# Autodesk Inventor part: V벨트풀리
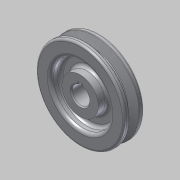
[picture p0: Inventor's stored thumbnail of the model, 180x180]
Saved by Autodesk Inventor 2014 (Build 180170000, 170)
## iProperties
Created: 2018-11
Part Number: V벨트풀리
Material: 알루미늄 6061
Document SubType Name: Modeling
Designer: mduedu
Density: 1 g/cm^3
Appearance: 알루미늄 - 평지
Author: mduedu
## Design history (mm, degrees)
sketch "스케치1"
  geometry: L1 (-9.5, 0)-(9.5, 0); L2 (9.5, 0)-(9.5, 42.7); L3 (9.5, 42.7)-(-9.5, 42.7); L4 (-9.5, 42.7)-(-9.5, 0); L5 (-4.877, 42.7)-(-1.953, 33.7); L6 (-1.953, 33.7)-(1.953, 33.7); L7 (1.953, 33.7)-(4.877, 42.7); L8 (0, 0)-(0, 42.7); L9 (-9.5, 40)-(9.5, 40); 3 further points
  constraints: 18 end point, 8 point on line, 3 perpendicular, 2 midpoint, 2 parallel, 1 coincident, 1 horizontal, 1 other
  dimensions: "d0" = 85.4 diameter of L3 L1; "d2" = 19 distance of L2.end L3.end; "d3" = 80 diameter of L9 L1; "d4" = 36 deg angle of L7 L5; "d5" = 6.3 distance between parallel lines of L6 L9; "d6" = 8 distance of point (4, 40) point (-4, 40)
revolve "회전1" sketch "스케치1" stored, may be unused: angle "d7" = 90 deg
sketch "스케치2"
  geometry: L1 (-2.5, 8.124)-(2.5, 8.124); L2 (2.5, 8.124)-(2.5, 10.8); L3 (2.5, 10.8)-(-2.5, 10.8); L4 (-2.5, 10.8)-(-2.5, 8.124); A1 r 8.5 centre (0, 0) between (-2.5, 8.124) and (2.5, 8.124); 1 further point
  constraints: 8 end point, 2 parallel, 2 point on circle, 1 centre point, 1 coincident, 1 horizontal, 1 perpendicular
  dimensions: "d8" = 17 diameter of A1; "d10" = 19.3 dimension on A1 L3; "d11" = 5 distance of L2.end L3.end
extrude "돌출1" cut sketch "스케치2" stored distance "d12" = 10; taper "d13" = 0 deg
chamfer "모따기1" distance "d14" = 1; stored, may be unused: second distance "d15" = 2, angle "d16" = 45 deg
fillet "모깎기1" dims "d17" = 1, "d18" = 0.5, "d19" = 2
sketch "스케치3"
  geometry: C1 r 17.5 at (0, 0); C2 r 28.5 at (0, 0); 1 further point
  constraints: 2 centre point, 2 coincident
  dimensions: "d20" = 35 diameter of C1; "d23" = 57 diameter of C2
extrude "돌출2" cut sketch "스케치3" distance "d24" = 9.5; taper "d25" = 0 deg
fillet "모깎기2" dims "d26" = 3
node "솔리드1"
